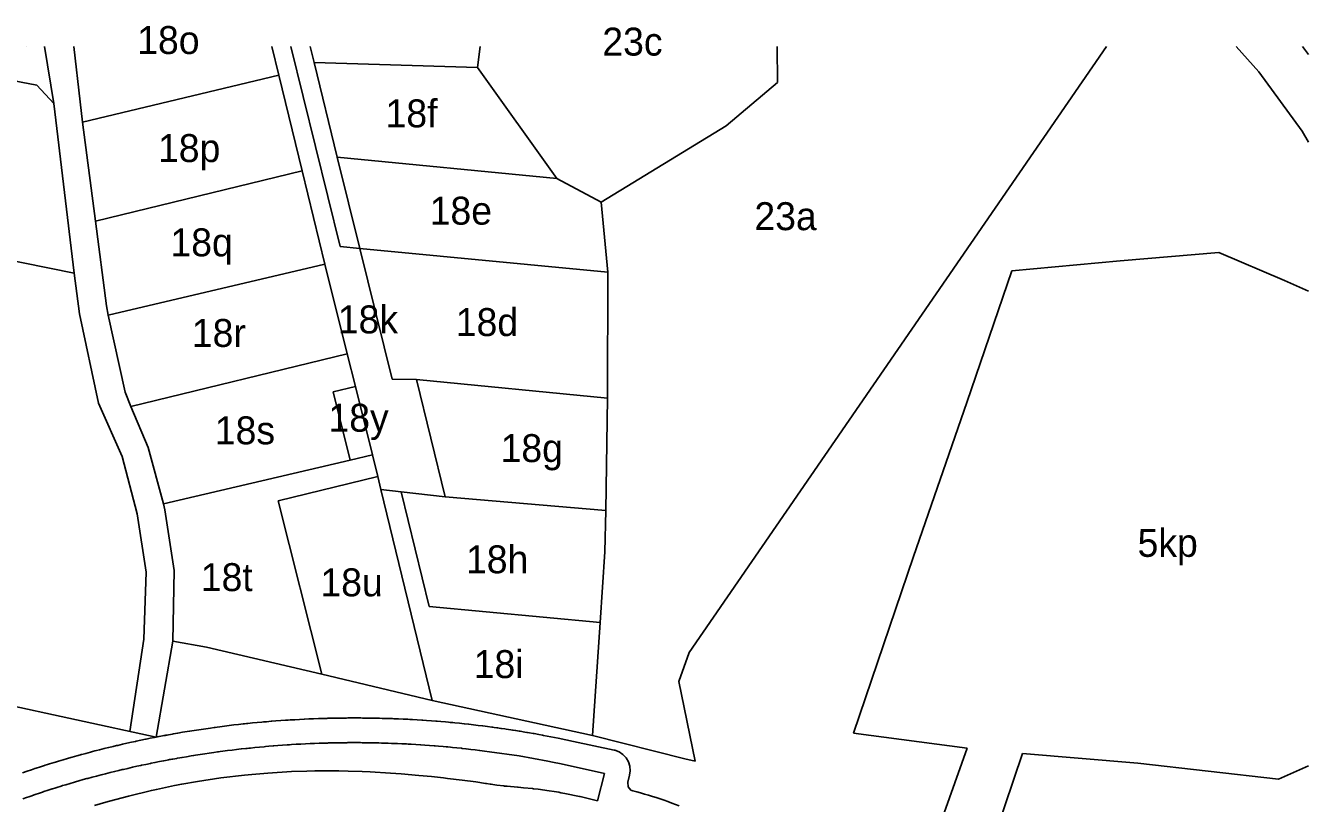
# Model space of a CAD drawing. Extents: x 702630 to 703245, y 6205279 to 6205714.
# Drawn here: x 702969.7 to 703245.1, y 6205547.5 to 6205714.5 of the extents above; entities that cross this region are included whole.
import ezdxf

# ---------------------------------------------------------------- set-up
doc = ezdxf.new("R2010")
doc.units = 0
for name, color, linetype in [('Matrikelnummer', 7, 'Continuous'), ('Matrikelnummer punkt', 7, 'Continuous'), ('Matrikelskel Almindeligt', 7, 'Continuous'), ('Matrikelskel Vej', 7, 'Continuous'), ('Optaget vej', 7, 'Continuous')]:
    doc.layers.add(name, color=color, linetype=linetype)

msp = doc.modelspace()

# ---------------------------------------------------------------- linework, layer by layer
at = {"layer": 'Matrikelnummer punkt'}
for p, q in [((703051.44, 6205695.62), (703051.44, 6205695.62)), ((703002.95, 6205688.17), (703002.95, 6205688.17)), ((703061.26, 6205674.73), (703061.26, 6205674.73)), ((703130.97, 6205673.55), (703130.97, 6205673.55)), ((703005.68, 6205667.93), (703005.68, 6205667.93)), ((703041.63, 6205651.38), (703041.63, 6205651.38)), ((703067.06, 6205650.81), (703067.06, 6205650.81)), ((703009.9, 6205648.48), (703009.9, 6205648.48)), ((703039.64, 6205630.28), (703039.64, 6205630.28)), ((703015.01, 6205627.57), (703015.01, 6205627.57)), ((703076.62, 6205623.75), (703076.62, 6205623.75)), ((703213.1, 6205603.41), (703213.1, 6205603.41)), ((703069.08, 6205599.88), (703069.08, 6205599.88)), ((703011.53, 6205596.05), (703011.53, 6205596.05)), ((703037.89, 6205594.94), (703037.89, 6205594.94)), ((703069.96, 6205577.38), (703069.96, 6205577.38))]:
    msp.add_line(p, q, dxfattribs=at)
at = {"layer": 'Matrikelskel Almindeligt'}
for p, q in [((703067.29, 6205710), (703066.74, 6205705.5)), ((703201.81, 6205710), (703112.17, 6205579.86)), ((703131.14, 6205702.27), (703131.1, 6205710)), ((703031.67, 6205706.58), (703066.74, 6205705.5)), ((702981.96, 6205693.73), (703024.1, 6205703.85)), ((703066.74, 6205705.5), (703083.78, 6205681.65)), ((703120.13, 6205692.93), (703131.14, 6205702.27)), ((703093.33, 6205676.54), (703120.13, 6205692.93)), ((703036.64, 6205686.23), (703083.78, 6205681.65)), ((702984.71, 6205672.5), (703029.1, 6205683.3)), ((703083.78, 6205681.65), (703093.33, 6205676.54)), ((703093.33, 6205676.54), (703094.76, 6205661.56)), ((702980.12, 6205661.33), (702951.51, 6205667.04)), ((703041.46, 6205666.58), (703094.76, 6205661.56)), ((703204.74, 6205663.99), (703225.92, 6205665.75)), ((703225.92, 6205665.75), (703240.01, 6205659.71)), ((702987.47, 6205652.28), (703034, 6205663.27)), ((703181.51, 6205661.84), (703204.74, 6205663.99)), ((703094.76, 6205661.56), (703094.67, 6205634.51)), ((703171.84, 6205633.53), (703181.51, 6205661.84)), ((703240.01, 6205659.71), (703245.14, 6205657.47)), ((702992.31, 6205632.71), (703038.76, 6205644.03)), ((703053.65, 6205638.46), (703094.67, 6205634.51)), ((703094.67, 6205634.51), (703094.28, 6205610.38)), ((703160.4, 6205600.46), (703171.84, 6205633.53)), ((702999.3, 6205611.76), (703039.41, 6205621.16)), ((703045.33, 6205617.67), (703023.92, 6205612.42)), ((703057.05, 6205569.6), (703046.02, 6205614.85)), ((703050.37, 6205614.38), (703056.34, 6205589.78)), ((703059.79, 6205613.29), (703094.28, 6205610.38)), ((703023.92, 6205612.42), (703033.34, 6205575.2)), ((703094.28, 6205610.38), (703094.1, 6205601.47)), ((703094.1, 6205601.47), (703093.12, 6205586.34)), ((703147.45, 6205562.59), (703160.4, 6205600.46)), ((703056.34, 6205589.78), (703093.12, 6205586.34)), ((703093.12, 6205586.34), (703091.46, 6205562.03)), ((703008.59, 6205581), (703001.37, 6205582.33)), ((703033.34, 6205575.2), (703008.59, 6205581)), ((703112.17, 6205579.86), (703109.96, 6205573.62)), ((703057.05, 6205569.6), (703033.34, 6205575.2)), ((703109.96, 6205573.62), (703113.51, 6205556.51)), ((702957.55, 6205570.41), (702997.74, 6205561.71)), ((703091.46, 6205562.03), (703057.05, 6205569.6)), ((703111.3, 6205557.05), (703091.46, 6205562.03)), ((703171.89, 6205559.35), (703147.45, 6205562.59)), ((703160.01, 6205526.05), (703171.89, 6205559.35)), ((703183.8, 6205558.17), (703171.51, 6205521.95)), ((703208.51, 6205556.11), (703183.8, 6205558.17)), ((703113.51, 6205556.51), (703111.3, 6205557.05)), ((703238.75, 6205552.66), (703208.51, 6205556.11)), ((703245.14, 6205555.51), (703238.75, 6205552.66))]:
    msp.add_line(p, q, dxfattribs=at)
at = {"layer": 'Matrikelskel Vej'}
for p, q in [((702969.82, 6205710), (702969.86, 6205709.99)), ((702969.86, 6205709.99), (702969.86, 6205710)), ((702973.75, 6205710), (702975.78, 6205697.77)), ((702981.41, 6205698.07), (702980.08, 6205710)), ((703024.1, 6205703.85), (703022.61, 6205710)), ((703026.64, 6205710), (703037.23, 6205667.03)), ((703030.84, 6205710), (703031.67, 6205706.58)), ((703229.63, 6205710), (703234.49, 6205704.54)), ((703243.86, 6205710), (703245.14, 6205708.25)), ((703031.67, 6205706.58), (703036.64, 6205686.23)), ((702953.4, 6205705.3), (702972.11, 6205701.65)), ((703029.1, 6205683.3), (703024.1, 6205703.85)), ((703234.49, 6205704.54), (703243.8, 6205691.79)), ((702972.11, 6205701.65), (702975.78, 6205697.77)), ((702975.78, 6205697.77), (702980.12, 6205661.33)), ((702981.96, 6205693.73), (702981.41, 6205698.07)), ((702984.71, 6205672.5), (702981.96, 6205693.73)), ((703243.8, 6205691.79), (703245.14, 6205689.41)), ((703036.64, 6205686.23), (703041.46, 6205666.58)), ((703034, 6205663.27), (703029.1, 6205683.3)), ((702987.08, 6205654.33), (702984.71, 6205672.5)), ((703037.23, 6205667.03), (703041.46, 6205666.58)), ((703041.46, 6205666.58), (703048.43, 6205638.58)), ((703038.76, 6205644.03), (703034, 6205663.27)), ((702987.47, 6205652.28), (702987.08, 6205654.33)), ((702991.1, 6205635.75), (702987.47, 6205652.28)), ((703040.53, 6205636.96), (703038.76, 6205644.03)), ((703048.43, 6205638.58), (703053.65, 6205638.46)), ((703053.65, 6205638.46), (703059.79, 6205613.29)), ((702992.31, 6205632.71), (702991.1, 6205635.75)), ((703040.53, 6205636.96), (703035.74, 6205635.82)), ((703035.74, 6205635.82), (703039.41, 6205621.16)), ((703044.19, 6205622.28), (703040.53, 6205636.96)), ((702996.07, 6205623.92), (702992.31, 6205632.71)), ((702999.3, 6205611.76), (702996.07, 6205623.92)), ((703039.41, 6205621.16), (703044.19, 6205622.28)), ((703045.33, 6205617.67), (703044.19, 6205622.28)), ((703046.02, 6205614.85), (703045.33, 6205617.67)), ((703046.02, 6205614.85), (703050.37, 6205614.38)), ((703059.79, 6205613.29), (703050.37, 6205614.38)), ((702999.6, 6205610.47), (702999.3, 6205611.76)), ((703001.6, 6205597.47), (702999.6, 6205610.47)), ((703001.37, 6205582.33), (703001.6, 6205597.47)), ((702997.74, 6205561.71), (703001.37, 6205582.33))]:
    msp.add_line(p, q, dxfattribs=at)
at = {"layer": 'Optaget vej'}
for p, q in [((702980.12, 6205661.33), (702981.27, 6205652.55)), ((702981.27, 6205652.55), (702985.4, 6205633.43)), ((702985.4, 6205633.43), (702990.46, 6205621.93)), ((702990.46, 6205621.93), (702993.66, 6205609.64)), ((702993.66, 6205609.64), (702995.59, 6205597.11)), ((702995.59, 6205597.11), (702995.1, 6205582.71)), ((702995.1, 6205582.71), (702992.13, 6205562.93)), ((703084.07, 6205561.51), (703080.91, 6205562.09)), ((703084.07, 6205561.51), (703087.36, 6205560.8)), ((703096.08, 6205558.91), (703087.36, 6205560.8)), ((703075.68, 6205557.71), (703069.35, 6205558.58)), ((703084.69, 6205555.95), (703094.05, 6205553.93)), ((703094.05, 6205553.93), (703092.53, 6205548.06)), ((703099.02, 6205552.01), (703099.41, 6205553.51))]:
    msp.add_line(p, q, dxfattribs=at)
for points in [[(703057.85, 6205565.13), (703057.84, 6205565.13), (703056.84, 6205565.21), (703055.83, 6205565.28), (703054.98, 6205565.34), (703054.82, 6205565.35), (703053.81, 6205565.41), (703052.8, 6205565.47), (703052.19, 6205565.51), (703051.79, 6205565.53), (703050.89, 6205565.57), (703050.78, 6205565.58), (703049.77, 6205565.62), (703048.76, 6205565.66), (703048.51, 6205565.67), (703047.75, 6205565.7), (703046.74, 6205565.73), (703046.27, 6205565.74), (703045.72, 6205565.76), (703044.71, 6205565.78), (703043.92, 6205565.79), (703043.7, 6205565.79), (703042.69, 6205565.81), (703042.06, 6205565.81), (703041.68, 6205565.82), (703040.67, 6205565.82), (703040.35, 6205565.82), (703039.65, 6205565.82), (703038.9, 6205565.82), (703038.64, 6205565.81), (703037.63, 6205565.8), (703036.77, 6205565.79), (703036.72, 6205565.79), (703036.62, 6205565.79), (703035.61, 6205565.77), (703034.6, 6205565.75), (703034.42, 6205565.74), (703033.58, 6205565.72), (703032.58, 6205565.69), (703031.57, 6205565.65), (703031.39, 6205565.64), (703030.98, 6205565.62), (703030.55, 6205565.61), (703029.58, 6205565.56), (703029.54, 6205565.56), (703028.54, 6205565.51), (703028.51, 6205565.51), (703027.52, 6205565.45), (703026.52, 6205565.39), (703026.08, 6205565.36), (703025.5, 6205565.33), (703024.49, 6205565.26), (703023.48, 6205565.18), (703022.61, 6205565.11), (703022.47, 6205565.1), (703021.47, 6205565.02), (703020.77, 6205564.96), (703020.46, 6205564.93), (703019.45, 6205564.84), (703018.45, 6205564.74), (703017.44, 6205564.64), (703017.13, 6205564.61), (703016.71, 6205564.56), (703016.43, 6205564.53), (703015.47, 6205564.43), (703015.42, 6205564.42), (703014.42, 6205564.31), (703013.42, 6205564.19), (703012.41, 6205564.06), (703011.41, 6205563.93), (703010.83, 6205563.86), (703010.41, 6205563.8), (703010.19, 6205563.77), (703009.4, 6205563.66), (703008.4, 6205563.52), (703007.4, 6205563.37), (703006.4, 6205563.22), (703005.41, 6205563.06), (703004.97, 6205562.99), (703004.92, 6205562.99), (703004.4, 6205562.9), (703003.41, 6205562.74), (703002.41, 6205562.57), (703001.42, 6205562.39), (703001.36, 6205562.38), (703001.25, 6205562.36), (703000.42, 6205562.21), (703000.14, 6205562.16), (702999.85, 6205562.11), (702999.68, 6205562.08), (702999.42, 6205562.03), (702999.13, 6205561.98), (702998.43, 6205561.84), (702998.35, 6205561.83), (702997.74, 6205561.71)], [(703069.92, 6205563.85), (703069.86, 6205563.85), (703068.91, 6205563.98), (703067.92, 6205564.11), (703067.86, 6205564.11), (703066.91, 6205564.23), (703065.9, 6205564.35), (703064.9, 6205564.46), (703064.81, 6205564.47), (703063.99, 6205564.56), (703063.89, 6205564.57), (703062.89, 6205564.67), (703061.88, 6205564.78), (703061.43, 6205564.82), (703060.87, 6205564.87), (703060.52, 6205564.9), (703059.86, 6205564.96), (703058.86, 6205565.05), (703058.1, 6205565.11), (703057.85, 6205565.13)], [(703069.92, 6205563.85), (703070.07, 6205563.83), (703070.31, 6205563.79), (703070.92, 6205563.71), (703071.15, 6205563.68), (703071.38, 6205563.65), (703071.75, 6205563.59), (703071.93, 6205563.57), (703072.65, 6205563.46), (703072.93, 6205563.42), (703073.92, 6205563.27), (703074.29, 6205563.22), (703074.42, 6205563.2), (703074.92, 6205563.12), (703075.01, 6205563.1), (703075.33, 6205563.05), (703075.73, 6205562.99), (703075.93, 6205562.96), (703076.92, 6205562.79), (703077.35, 6205562.72), (703077.44, 6205562.71), (703077.92, 6205562.62), (703078.67, 6205562.5), (703078.92, 6205562.45), (703079.91, 6205562.27), (703080.68, 6205562.13), (703080.91, 6205562.09)], [(702997.74, 6205561.71), (702997.43, 6205561.65), (702996.44, 6205561.45), (702995.59, 6205561.28), (702995.45, 6205561.25), (702994.46, 6205561.04), (702993.47, 6205560.83), (702993.33, 6205560.8), (702992.48, 6205560.62), (702991.49, 6205560.4), (702990.51, 6205560.17), (702989.53, 6205559.94), (702989.26, 6205559.88), (702988.54, 6205559.71), (702987.57, 6205559.48), (702987.55, 6205559.47), (702986.57, 6205559.23), (702985.59, 6205558.98), (702984.96, 6205558.82), (702984.61, 6205558.73), (702984.09, 6205558.6), (702983.63, 6205558.48), (702982.66, 6205558.22), (702981.83, 6205557.99), (702981.68, 6205557.95)], [(703057.43, 6205559.85), (703056.45, 6205559.92), (703055.46, 6205559.99), (703054.62, 6205560.05), (703054.48, 6205560.06), (703053.49, 6205560.12), (703052.5, 6205560.18), (703051.9, 6205560.21), (703051.52, 6205560.23), (703050.63, 6205560.28), (703050.53, 6205560.28), (703049.55, 6205560.33), (703048.56, 6205560.37), (703048.32, 6205560.37), (703047.57, 6205560.4), (703046.58, 6205560.43), (703046.13, 6205560.44), (703045.6, 6205560.46), (703044.61, 6205560.48), (703043.83, 6205560.49), (703043.62, 6205560.5), (703042.63, 6205560.51), (703042.01, 6205560.51), (703041.65, 6205560.52), (703040.66, 6205560.52), (703040.35, 6205560.52), (703039.67, 6205560.52), (703038.94, 6205560.52), (703038.69, 6205560.51), (703037.7, 6205560.5), (703036.85, 6205560.49), (703036.81, 6205560.49), (703036.71, 6205560.49), (703035.72, 6205560.47), (703034.73, 6205560.45), (703034.57, 6205560.44), (703033.75, 6205560.42), (703032.76, 6205560.39), (703031.77, 6205560.35), (703031.61, 6205560.35), (703031.21, 6205560.33), (703030.79, 6205560.31), (703029.83, 6205560.27), (703029.8, 6205560.26), (703028.81, 6205560.21), (703028.79, 6205560.21), (703027.83, 6205560.16), (703026.84, 6205560.1), (703026.42, 6205560.07), (703025.86, 6205560.04), (703024.87, 6205559.97), (703023.89, 6205559.9), (703023.02, 6205559.83), (703022.9, 6205559.82), (703021.92, 6205559.74), (703021.23, 6205559.68), (703020.93, 6205559.65), (703019.95, 6205559.56), (703018.97, 6205559.47), (703017.98, 6205559.37), (703017.68, 6205559.34), (703017.27, 6205559.29), (703017, 6205559.26), (703016.06, 6205559.16), (703016.02, 6205559.16), (703015.04, 6205559.04), (703014.06, 6205558.92), (703013.08, 6205558.8), (703012.1, 6205558.68), (703011.53, 6205558.6), (703011.12, 6205558.55), (703010.91, 6205558.52), (703010.14, 6205558.41), (703009.16, 6205558.27), (703008.19, 6205558.13), (703007.21, 6205557.98), (703006.23, 6205557.83), (703005.81, 6205557.76), (703005.77, 6205557.75), (703005.26, 6205557.67), (703004.29, 6205557.51), (703003.31, 6205557.34), (703002.34, 6205557.17), (703002.29, 6205557.16), (703002.19, 6205557.15), (703001.37, 6205557), (703001.1, 6205556.95), (703000.81, 6205556.9), (703000.65, 6205556.87), (703000.4, 6205556.82), (703000.12, 6205556.77), (702999.43, 6205556.63), (702999.35, 6205556.62), (702998.46, 6205556.45), (702997.49, 6205556.25), (702996.66, 6205556.08), (702996.52, 6205556.06), (702995.55, 6205555.86), (702994.59, 6205555.65), (702994.45, 6205555.62), (702993.62, 6205555.44), (702992.66, 6205555.23), (702991.7, 6205555), (702990.73, 6205554.78), (702990.48, 6205554.72), (702989.77, 6205554.55), (702988.82, 6205554.32), (702988.81, 6205554.32), (702987.85, 6205554.09), (702986.9, 6205553.84), (702986.28, 6205553.69), (702985.94, 6205553.6), (702985.43, 6205553.47), (702984.98, 6205553.35), (702984.03, 6205553.1), (702983.08, 6205552.84)], [(702969.09, 6205554.05), (702970.04, 6205554.38), (702971, 6205554.71), (702971.69, 6205554.95), (702971.97, 6205555.04), (702972.93, 6205555.36), (702973.78, 6205555.63), (702973.91, 6205555.67), (702974.42, 6205555.83), (702974.88, 6205555.98), (702975.84, 6205556.27), (702976.14, 6205556.36), (702976.82, 6205556.56), (702977.79, 6205556.85), (702978.75, 6205557.13), (702978.95, 6205557.19), (702979.73, 6205557.41), (702980.7, 6205557.68), (702981.5, 6205557.9), (702981.68, 6205557.95)], [(703057.43, 6205559.85), (703057.67, 6205559.83), (703058.41, 6205559.77), (703059.4, 6205559.68), (703060.04, 6205559.62), (703060.38, 6205559.59), (703060.93, 6205559.54), (703061.36, 6205559.5), (703062.35, 6205559.4), (703063.33, 6205559.3), (703063.43, 6205559.29), (703064.23, 6205559.2), (703064.31, 6205559.19), (703065.29, 6205559.08), (703066.27, 6205558.97), (703067.21, 6205558.85), (703067.25, 6205558.85), (703068.23, 6205558.72), (703069.35, 6205558.58)], [(703099.41, 6205553.51), (703099.55, 6205554.49), (703099.46, 6205555.48), (703099.16, 6205556.42), (703098.66, 6205557.27), (703097.97, 6205557.99), (703097.15, 6205558.53), (703096.22, 6205558.88), (703096.15, 6205558.9), (703096.08, 6205558.91)], [(703084.69, 6205555.95), (703082.85, 6205556.32), (703081.88, 6205556.51), (703075.68, 6205557.71)], [(702969.14, 6205548.43), (702969.93, 6205548.72), (702970.39, 6205548.89), (702970.85, 6205549.05), (702971.78, 6205549.38), (702972.71, 6205549.7), (702973.38, 6205549.92), (702973.64, 6205550.01), (702974.57, 6205550.32), (702975.4, 6205550.58), (702975.51, 6205550.62), (702976.01, 6205550.78), (702976.44, 6205550.91), (702977.38, 6205551.2), (702977.66, 6205551.29), (702978.33, 6205551.48), (702979.28, 6205551.76), (702980.22, 6205552.04), (702980.41, 6205552.09), (702981.17, 6205552.31), (702982.12, 6205552.58), (702982.9, 6205552.79), (702983.08, 6205552.84)], [(703092.53, 6205548.06), (703088.78, 6205548.93), (703088.62, 6205548.97), (703085.48, 6205549.63), (703084.67, 6205549.78), (703084.23, 6205549.86), (703083.23, 6205550.03), (703082.16, 6205550.2), (703079.81, 6205550.52), (703079.8, 6205550.52), (703078.81, 6205550.63), (703078.57, 6205550.66), (703076.63, 6205550.85), (703075.45, 6205550.94), (703075.36, 6205550.95), (703073.12, 6205551.15), (703072.56, 6205551.21), (703072.44, 6205551.22), (703070.89, 6205551.42), (703070.03, 6205551.54), (703069.68, 6205551.59), (703069.46, 6205551.62), (703068.67, 6205551.74), (703068.45, 6205551.78), (703066.37, 6205552.08), (703063.48, 6205552.46), (703060.29, 6205552.85), (703059.43, 6205552.95), (703056.91, 6205553.22), (703054.19, 6205553.49), (703050.33, 6205553.81), (703048.08, 6205553.97), (703043.73, 6205554.23), (703041.96, 6205554.32), (703038.97, 6205554.42), (703036.95, 6205554.46), (703036.91, 6205554.46), (703031.84, 6205554.46), (703030.11, 6205554.42), (703026.79, 6205554.3), (703021.73, 6205554), (703018.27, 6205553.7), (703016.69, 6205553.55), (703011.67, 6205552.95), (703006.66, 6205552.19), (703003.28, 6205551.6), (703003.18, 6205551.58), (703002.12, 6205551.38), (703001.68, 6205551.3), (702997.8, 6205550.49), (702996.73, 6205550.25), (702991.81, 6205549.06), (702987.75, 6205547.96), (702986.93, 6205547.73), (702984.49, 6205547)], [(703099.67, 6205550.29), (703099.07, 6205551.05), (703099.02, 6205552.01)], [(703110.08, 6205546.92), (703109.27, 6205547.24), (703108.45, 6205547.55), (703107.63, 6205547.86), (703106.8, 6205548.15), (703105.97, 6205548.44), (703105.14, 6205548.72), (703104.31, 6205548.98), (703103.47, 6205549.24), (703102.63, 6205549.49), (703101.78, 6205549.73), (703100.94, 6205549.96), (703100.09, 6205550.18), (703099.88, 6205550.24), (703099.67, 6205550.29)]]:
    msp.add_lwpolyline(points, dxfattribs=at)

# ---------------------------------------------------------------- texts
at = {"layer": 'Matrikelnummer'}
for s, p in [('18o', (702993.69, 6205708.37)), ('23c', (703093.55, 6205708.03)), ('18f', (703047.01, 6205692.62)), ('18p', (702998.15, 6205685.17)), ('18e', (703056.48, 6205671.73)), ('23a', (703126.2, 6205670.55)), ('18q', (703000.82, 6205664.93)), ('18k', (703036.76, 6205648.38)), ('18d', (703062.09, 6205647.81)), ('18r', (703005.42, 6205645.48)), ('18y', (703034.75, 6205627.28)), ('18s', (703010.35, 6205624.57)), ('18g', (703071.71, 6205620.75)), ('5kp', (703208.47, 6205600.41)), ('18h', (703064.28, 6205596.88)), ('18t', (703007.34, 6205593.05)), ('18u', (703033.02, 6205591.94)), ('18i', (703065.93, 6205574.38))]:
    msp.add_text(s, height=6, dxfattribs=at).set_placement(p)

doc.saveas('drawing.dxf')
